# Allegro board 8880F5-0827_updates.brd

Outline 581.66 x 429.26 mm; copper layers: TOP, L02_DGND, L03_SIGNAL, L04_DGND, L05_SIGNAL, L06_DGND, L07_SIGNAL, L08_DGND, L09_SIGNAL, L10_DGND, L11_POWER, L12_DGND, L13_POWER, L14_DGND, L15_POWER, L16_DGND, L17_5V, L18_CBIT, L19_DGND, L20_POWER, L21_DGND, L22_POWER, L23_DGND, L24_POWER, L25_DGND, L26_SIGNAL, L27_DGND, L28_SIGNAL, L29_DGND, L30_SIGNAL, L31_DGND, L32_SIGNAL, L33_DGND, BOTTOM. Coordinates in mm from the lower left corner of the outline.

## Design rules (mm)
net group DIFFPAIR0: nets D31702 D31704
net group DIFFPAIR1: nets D31706 D31708
net group DIFFPAIR2: nets D31710 D31712
net group DIFFPAIR3: nets D31714 D31716
net group DIFFPAIR4: nets D32102 D32104
net group DIFFPAIR5: nets D32106 D32108
net group DIFFPAIR6: nets D32110 D32112
net group DIFFPAIR7: nets D32114 D32116
net group DIFFPAIR8: nets D30102 D30104
net group DIFFPAIR9: nets D30106 D30108
net group DIFFPAIR10: nets D30110 D30112
net group DIFFPAIR11: nets D30114 D30116
net group DIFFPAIR12: nets D30502 D30504
net group DIFFPAIR13: nets D30506 D30508
net group DIFFPAIR14: nets D30510 D30512
net group DIFFPAIR15: nets D30514 D30516
net group DIFFPAIR16: nets D13102 D13104
net group DIFFPAIR17: nets D13114 D13116
net group DIFFPAIR18: nets D13101 D13103
net group DIFFPAIR19: nets D13113 D13115
net group DIFFPAIR20: nets D13202 D13204
net group DIFFPAIR21: nets D13206 D13208
net group DIFFPAIR22: nets D13210 D13212
net group DIFFPAIR23: nets D13214 D13216
net group DIFFPAIR24: nets D13201 D13203
net group DIFFPAIR25: nets D13205 D13207
net group DIFFPAIR26: nets D13209 D13211
net group DIFFPAIR27: nets D13213 D13215
net group DIFFPAIR28: nets D11902 D11904
net group DIFFPAIR29: nets D11901 D11903
net group DIFFPAIR30: nets D11914 D11916
net group DIFFPAIR31: nets D11913 D11915
net group DIFFPAIR32: nets D12002 D12004
net group DIFFPAIR33: nets D12006 D12008
net group DIFFPAIR34: nets D12010 D12012
net group DIFFPAIR35: nets D12014 D12016
net group DIFFPAIR36: nets D12001 D12003
net group DIFFPAIR37: nets D12005 D12007
net group DIFFPAIR38: nets D12009 D12011
net group DIFFPAIR39: nets D12013 D12015
net group DIFFPAIR40: nets D10802 D10804
net group DIFFPAIR41: nets D10806 D10808
net group DIFFPAIR42: nets D10810 D10812
net group DIFFPAIR43: nets D10814 D10816
net group DIFFPAIR44: nets D10801 D10803
net group DIFFPAIR45: nets D10805 D10807
net group DIFFPAIR46: nets D10809 D10811
net group DIFFPAIR47: nets D10813 D10815
net group DIFFPAIR48: nets D10702 D10704
net group DIFFPAIR49: nets D10701 D10703
net group DIFFPAIR50: nets D10714 D10716
net group DIFFPAIR51: nets D10713 D10715
net group DIFFPAIR52: nets D11013 D11015
net group DIFFPAIR53: nets D11014 D11016
net group DIFFPAIR54: nets D11001 D11003
net group DIFFPAIR55: nets D11002 D11004
net group DIFFPAIR56: nets D10913 D10915
net group DIFFPAIR57: nets D10914 D10916
net group DIFFPAIR58: nets D10909 D10911
net group DIFFPAIR59: nets D10910 D10912
net group DIFFPAIR60: nets D10905 D10907
net group DIFFPAIR61: nets D10906 D10908
net group DIFFPAIR62: nets D10901 D10903
net group DIFFPAIR63: nets D10902 D10904
net group DIFFPAIR77: nets S1_ISP14+ S1_ISP14-
net group DIFFPAIR91: nets S1_ISP00+ S1_ISP00-
net group DIFFPAIR105: nets S2_ISP14+ S2_ISP14-
net group DIFFPAIR119: nets S2_ISP00+ S2_ISP00-
net group DIFFPAIR133: nets S4_ISP14+ S4_ISP14-
net group DIFFPAIR147: nets S4_ISP00+ S4_ISP00-
net group DIFFPAIR161: nets S3_ISP14+ S3_ISP14-
net group DIFFPAIR175: nets S3_ISP00+ S3_ISP00-
net group DIFFPAIR176: nets D12206 D12208
net group DIFFPAIR177: nets D12313 D12315
net group DIFFPAIR178: nets D12210 D12212
net group DIFFPAIR179: nets D11806 D11808
net group DIFFPAIR180: nets D11805 D11807
net group DIFFPAIR181: nets D12310 D12312
net group DIFFPAIR182: nets D11810 D11812
net group DIFFPAIR183: nets D11802 D11804
net group DIFFPAIR184: nets D11910 D11912
net group DIFFPAIR185: nets D11909 D11911
net group DIFFPAIR186: nets D11906 D11908
net group DIFFPAIR187: nets D11801 D11803
net group DIFFPAIR188: nets D11813 D11815
net group DIFFPAIR189: nets D11809 D11811
net group DIFFPAIR190: nets D12302 D12304
net group DIFFPAIR191: nets D12305 D12307
net group DIFFPAIR192: nets D12301 D12303
net group DIFFPAIR193: nets D12205 D12207
net group DIFFPAIR194: nets D12209 D12211
net group DIFFPAIR195: nets D12309 D12311
net group DIFFPAIR196: nets D12314 D12316
net group DIFFPAIR197: nets D12213 D12215
net group DIFFPAIR198: nets D12214 D12216
net group DIFFPAIR199: nets D12201 D12203
net group DIFFPAIR200: nets D12202 D12204
net group DIFFPAIR201: nets D11905 D11907
net group DIFFPAIR202: nets D10610 D10612
net group DIFFPAIR203: nets D10609 D10611
net group DIFFPAIR204: nets D10606 D10608
net group DIFFPAIR205: nets D10605 D10607
net group DIFFPAIR206: nets D10313 D10315
net group DIFFPAIR207: nets D10314 D10316
net group DIFFPAIR208: nets D10305 D10307
net group DIFFPAIR209: nets D10302 D10304
net group DIFFPAIR210: nets D10214 D10216
net group DIFFPAIR211: nets D10213 D10215
net group DIFFPAIR212: nets D10201 D10203
net group DIFFPAIR213: nets D10202 D10204
net group DIFFPAIR214: nets D10613 D10615
net group DIFFPAIR215: nets D10206 D10208
net group DIFFPAIR216: nets D10205 D10207
net group DIFFPAIR217: nets D10209 D10211
net group DIFFPAIR218: nets D10306 D10308
net group DIFFPAIR219: nets D10210 D10212
net group DIFFPAIR220: nets D10301 D10303
net group DIFFPAIR221: nets D10309 D10311
net group DIFFPAIR222: nets D10614 D10616
net group DIFFPAIR223: nets D10601 D10603
net group DIFFPAIR224: nets D10602 D10604
net group DIFFPAIR225: nets D10705 D10707
net group DIFFPAIR226: nets D10706 D10708
net group DIFFPAIR227: nets D10710 D10712
net group DIFFPAIR228: nets D11213 D11215
net group DIFFPAIR229: nets D11206 D11208
net group DIFFPAIR230: nets D11209 D11211
net group DIFFPAIR231: nets D11610 D11612
net group DIFFPAIR232: nets D11601 D11603
net group DIFFPAIR233: nets D11602 D11604
net group DIFFPAIR234: nets D11605 D11607
net group DIFFPAIR235: nets D11006 D11008
net group DIFFPAIR236: nets D11113 D11115
net group DIFFPAIR237: nets D11110 D11112
net group DIFFPAIR238: nets D11009 D11011
net group DIFFPAIR239: nets D11010 D11012
net group DIFFPAIR240: nets D11005 D11007
net group DIFFPAIR241: nets D11613 D11615
net group DIFFPAIR242: nets D11606 D11608
net group DIFFPAIR243: nets D11201 D11203
net group DIFFPAIR244: nets D11210 D11212
net group DIFFPAIR245: nets D11205 D11207
net group DIFFPAIR246: nets D11202 D11204
net group DIFFPAIR247: nets D11609 D11611
net group DIFFPAIR248: nets D11114 D11116
net group DIFFPAIR249: nets D11101 D11103
net group DIFFPAIR250: nets D11106 D11108
net group DIFFPAIR251: nets D11109 D11111
net group DIFFPAIR252: nets D11214 D11216
net group DIFFPAIR253: nets D11105 D11107
net group DIFFPAIR254: nets D12913 D12915
net group DIFFPAIR255: nets D12909 D12911
net group DIFFPAIR256: nets D12905 D12907
net group DIFFPAIR257: nets D12901 D12903
net group DIFFPAIR258: nets D12906 D12908
net group DIFFPAIR259: nets D12910 D12912
net group DIFFPAIR260: nets D12902 D12904
net group DIFFPAIR261: nets D12914 D12916
net group DIFFPAIR262: nets D11413 D11415
net group DIFFPAIR263: nets D11414 D11416
net group DIFFPAIR264: nets D11313 D11315
net group DIFFPAIR265: nets D11309 D11311
net group DIFFPAIR266: nets D11314 D11316
net group DIFFPAIR267: nets D11405 D11407
net group DIFFPAIR268: nets D11410 D11412
net group DIFFPAIR269: nets D11501 D11503
net group DIFFPAIR270: nets D11406 D11408
net group DIFFPAIR271: nets D11505 D11507
net group DIFFPAIR272: nets D11506 D11508
net group DIFFPAIR273: nets D11502 D11504
net group DIFFPAIR274: nets D11310 D11312
net group DIFFPAIR275: nets D11302 D11304
net group DIFFPAIR276: nets D11306 D11308
net group DIFFPAIR277: nets D11305 D11307
net group DIFFPAIR278: nets D11301 D11303
net group DIFFPAIR279: nets D11401 D11403
net group DIFFPAIR280: nets D11402 D11404
net group DIFFPAIR281: nets D11102 D11104
net group DIFFPAIR282: nets D10709 D10711
net group DIFFPAIR283: nets D11814 D11816

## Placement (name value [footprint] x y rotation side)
BD29  BD120-3A-S8  [FB0805]  129.54 134.62 180 bottom
BD30  BD120-3A-S8  [FB0805]  129.54 146.05 180 bottom
BD31  BD120-3A-S8  [FB0805]  129.54 142.24 0 bottom
BD32  BD120-3A-S8  [FB0805]  513.08 238.76 180 bottom
BD33  BD120-3A-S8  [FB0805]  513.08 242.57 180 bottom
BD34  BD120-3A-S8  [FB0805]  453.64 145.54 0 bottom
BD35  BD120-3A-S8  [FB0805]  453.64 137.92 180 bottom
BD36  BD120-3A-S8  [FB0805]  129.54 138.43 180 bottom
BD37  BD120-3A-S8  [FB0805]  453.64 130.3 180 bottom
BD38  BD120-3A-S8  [FB0805]  513.08 242.57 180 bottom
BD39  BD120-3A-S8  [FB0805]  453.64 141.73 0 bottom
BD40  BD120-3A-S8  [FB0805]  453.64 134.11 180 bottom
BD41  BD120-3A-S8  [FB0805]  513.08 234.95 180 bottom
BD42  BD120-3A-S8  [FB0805]  513.08 231.14 180 bottom
BD43  BD120-3A-S8  [FB0805]  513.08 227.33 180 bottom
BD44  BD120-3A-S8  [FB0805]  129.54 149.86 180 bottom
BR902  330-1-S4  [R0402]  36.83 133.35 270 bottom
C3  0.1U-16-X-S4-MU  [C0402]  184.15 132.33 180 bottom
C4  0.1U-16-X-S4-MU  [C0402]  181.61 132.33 180 bottom
C5  22P-50-N-S4-AVX  [C0402]  221.21 277.48 90 bottom
C6  22P-50-N-S4-AVX  [C0402]  221.21 271.16 270 bottom
C7  0.1U-16-X-S4-MU  [C0402]  110.74 230.12 0 bottom
C8  0.1U-16-X-S4-MU  [C0402]  104.14 215.5 180 bottom
C9  0.1U-16-X-S4-MU  [C0402]  104.24 229.1 180 bottom
CA1  NC/10U-10-X6S-S6-MU  [C0603]  186.05 292.1 0 bottom
CA2  NC/47U-10-X5R-S8-TDK  [C0805]  186.16 294 0 bottom
CA3  NC/10U-10-X6S-S6-MU  [C0603]  174.62 292.1 180 bottom
CA4  NC/47U-10-X5R-S8-TDK  [C0805]  174.52 294 180 bottom
CA5  NC/10U-10-X6S-S6-MU  [C0603]  117.47 290.83 180 bottom
CA6  NC/47U-10-X5R-S8-TDK  [C0805]  117.37 292.74 180 bottom
CA7  NC/10U-10-X6S-S6-MU  [C0603]  169.54 292.1 0 bottom
CA8  NC/47U-10-X5R-S8-TDK  [C0805]  169.65 294 0 bottom
CA9  NC/10U-10-X6S-S6-MU  [C0603]  158.11 292.1 180 bottom
CA10  NC/47U-10-X5R-S8-TDK  [C0805]  158.01 294 180 bottom
CA11  NC/10U-10-X6S-S6-MU  [C0603]  186.05 275.59 0 bottom
CA12  NC/47U-10-X5R-S8-TDK  [C0805]  186.16 277.5 0 bottom
CA13  NC/47U-10-X5R-S8-TDK  [C0805]  202.16 294 0 bottom
CA14  NC/10U-10-X6S-S6-MU  [C0603]  202.06 292.1 0 bottom
CA15  NC/47U-10-X5R-S8-TDK  [C0805]  190.53 294 180 bottom
CA16  NC/10U-10-X6S-S6-MU  [C0603]  190.63 292.1 180 bottom
CA17  NC/47U-10-X5R-S8-TDK  [C0805]  169.65 277.5 0 bottom
CA18  NC/10U-10-X6S-S6-MU  [C0603]  169.54 275.59 0 bottom
CA19  NC/47U-10-X5R-S8-TDK  [C0805]  100.34 249.52 180 bottom
CA20  NC/10U-10-X6S-S6-MU  [C0603]  100.44 247.61 180 bottom
CA21  10U-10-X6S-S6-MU  [C0603]  186.05 289.56 0 bottom
CA22  10U-10-X6S-S6-MU  [C0603]  174.62 289.56 180 bottom
CA23  10U-10-X6S-S6-MU  [C0603]  117.47 288.29 180 bottom
CA24  10U-10-X6S-S6-MU  [C0603]  169.54 289.56 0 bottom
CA25  10U-10-X6S-S6-MU  [C0603]  158.11 289.56 180 bottom
CA26  10U-10-X6S-S6-MU  [C0603]  186.05 273.05 0 bottom
CA27  10U-10-X6S-S6-MU  [C0603]  202.06 289.56 0 bottom
CA28  10U-10-X6S-S6-MU  [C0603]  190.63 289.56 180 bottom
CA29  10U-10-X6S-S6-MU  [C0603]  169.54 273.05 0 bottom
CA30  NC/47U-10-X5R-S8-TDK  [C0805]  95.47 249.57 180 bottom
CA31  10U-10-X6S-S6-MU  [C0603]  95.57 247.66 180 bottom
CA32  NC/10U-10-X6S-S6-MU  [C0603]  202.06 275.59 0 bottom
CA33  NC/47U-10-X5R-S8-TDK  [C0805]  202.16 277.5 0 bottom
CA34  10U-10-X6S-S6-MU  [C0603]  202.06 273.05 0 bottom
CA35  NC/10U-10-X6S-S6-MU  [C0603]  174.62 275.59 180 bottom
CA36  NC/47U-10-X5R-S8-TDK  [C0805]  174.52 277.5 180 bottom
CA37  10U-10-X6S-S6-MU  [C0603]  174.62 273.05 180 bottom
CA38  NC/10U-10-X6S-S6-MU  [C0603]  158.11 275.59 180 bottom
CA39  NC/47U-10-X5R-S8-TDK  [C0805]  158.01 277.5 180 bottom
CA40  10U-10-X6S-S6-MU  [C0603]  158.11 273.05 180 bottom
CB1  0.1U-25-X-S6  [C0603]  116.84 130.81 0 bottom
CB2  10U-16-T-SA  [CODE_A]  116.84 128.27 0 bottom
CB3  0.1U-25-X-S6  [C0603]  472.44 130.81 0 bottom
CB4  10U-16-T-SA  [CODE_A]  472.44 128.27 0 bottom
CB5  0.1U-25-X-S6  [C0603]  556.51 300.99 0 bottom
CB6  10U-16-T-SA  [CODE_A]  556.51 298.45 0 bottom
CB7  0.1U-25-X-S6  [C0603]  223.52 298.45 0 bottom
CB8  10U-16-T-SA  [CODE_A]  223.52 295.91 0 bottom
CB9  0.1U-25-X-S6  [C0603]  23.01 130.71 0 bottom
CB10  10U-25-X7R-SA  [C1206]  22.86 128.27 0 bottom
CB11  0.1U-25-X-S6  [C0603]  484.02 130.71 0 bottom
CB12  10U-25-X7R-SA  [C1206]  483.87 128.27 0 bottom
CB13  0.1U-25-X-S6  [C0603]  547.52 300.89 0 bottom
CB14  10U-25-X7R-SA  [C1206]  547.37 298.45 0 bottom
CB15  0.1U-25-X-S6  [C0603]  12.45 262.13 0 bottom
CB16  10U-25-X7R-SA  [C1206]  12.3 259.69 0 bottom
CB19  0.1U-25-X7R-S4-MU  [C0402]  215.9 17.78 180 bottom
CC1  0.47U-10-X6S-S2-TY  [C0201]  237.98 224.12 90 bottom
CC2  4.7U-10-X6T-S4-MU  [C0402]  236.32 222.4 270 bottom
CC4  0.47U-10-X6S-S2-TY  [C0201]  229.81 247.93 0 bottom
CC6  0.47U-10-X6S-S2-TY  [C0201]  250.17 224.12 90 bottom
CC7  0.47U-10-X6S-S2-TY  [C0201]  229.81 246.66 0 bottom
CC8  0.47U-10-X6S-S2-TY  [C0201]  263.63 224.12 90 bottom
CC9  0.47U-10-X6S-S2-TY  [C0201]  254.61 266.16 270 bottom
CC11  0.47U-10-X6S-S2-TY  [C0201]  251.06 224.12 90 bottom
CC13  0.47U-10-X6S-S2-TY  [C0201]  256.77 224.12 90 bottom
CC15  4.7U-2.5-X6S-S2-MU  [C0201]  259.65 264.95 90 bottom
CC16  NC/4.7U-2.5-X6S-S2-MU  [C0201]  271.64 249.5 0 bottom
CC17  4.7U-2.5-X6S-S2-MU  [C0201]  229.81 253.69 0 bottom
CC19  0.47U-10-X6S-S2-TY  [C0201]  252.83 266.16 270 bottom
CC20  4.7U-10-X6T-S4-MU  [C0402]  254.11 267.66 0 bottom
CC22  0.47U-10-X6S-S2-TY  [C0201]  251.05 266.16 270 bottom
CC23  4.7U-10-X6T-S4-MU  [C0402]  250.34 253.09 270 bottom
CC25  0.47U-10-X6S-S2-TY  [C0201]  272.85 245.18 180 bottom
CC26  0.47U-10-X6S-S2-TY  [C0201]  253.72 266.16 270 bottom
CC27  0.47U-10-X6S-S2-TY  [C0201]  272.85 249.5 180 bottom
CC28  0.47U-10-X6S-S2-TY  [C0201]  259.65 266.16 270 bottom
CC29  0.47U-10-X6S-S2-TY  [C0201]  231.03 253.69 180 bottom
CC30  0.47U-10-X6S-S2-TY  [C0201]  229.81 243.41 0 bottom
CC31  0.47U-10-X6S-S2-TY  [C0201]  249.28 224.12 90 bottom
CC32  0.47U-10-X6S-S2-TY  [C0201]  262.36 224.12 90 bottom
CC33  0.47U-10-X6S-S2-TY  [C0201]  272.85 243.91 180 bottom
CC34  0.47U-10-X6S-S2-TY  [C0201]  251.94 266.16 270 bottom
CC35  0.47U-10-X6S-S2-TY  [C0201]  272.85 241.37 180 bottom
CC36  0.47U-10-X6S-S2-TY  [C0201]  272.85 242.64 180 bottom
CC37  0.47U-10-X6S-S2-TY  [C0201]  247.57 264.95 90 bottom
CC38  NC/4.7U-2.5-X6S-S2-MU  [C0201]  247.57 266.16 270 bottom
CC39  0.47U-10-X6S-S2-TY  [C0201]  231.03 249.2 180 bottom
CC40  4.7U-2.5-X6S-S2-MU  [C0201]  258.5 246.67 180 bottom
CC41  4.7U-2.5-X6S-S2-MU  [C0201]  229.81 249.2 0 bottom
CC42  4.7U-2.5-X6S-S2-MU  [C0201]  251.54 253.03 90 bottom
CD1  0.1U-10-X7R-S2-MU  [C0201]  237.98 225.34 270 top
CD3  0.1U-10-X7R-S2-MU  [C0201]  271.64 241.37 0 top
CD4  0.1U-10-X7R-S2-MU  [C0201]  254.61 264.95 90 top
CD5  0.1U-10-X7R-S2-MU  [C0201]  263.63 225.34 270 top
CD6  0.1U-10-X7R-S2-MU  [C0201]  231.03 246.66 180 top
CD7  0.1U-10-X7R-S2-MU  [C0201]  271.64 242.64 0 top
CD8  0.1U-10-X7R-S2-MU  [C0201]  251.06 225.34 270 top
CD9  0.1U-10-X7R-S2-MU  [C0201]  256.77 225.34 270 top
CD10  0.1U-10-X7R-S2-MU  [C0201]  271.64 249.5 0 top
CD11  0.1U-10-X7R-S2-MU  [C0201]  259.65 264.95 90 top
CD12  0.1U-10-X7R-S2-MU  [C0201]  231.03 253.69 180 top
CD13  0.1U-10-X7R-S2-MU  [C0201]  252.83 264.95 90 top
CD14  0.1U-10-X7R-S2-MU  [C0201]  251.05 264.95 90 top
CD15  0.1U-10-X7R-S2-MU  [C0201]  271.64 245.18 0 top
CD16  0.1U-10-X7R-S2-MU  [C0201]  253.72 264.95 90 top
CD17  0.1U-10-X7R-S2-MU  [C0201]  231.03 247.93 180 top
CD18  0.1U-10-X7R-S2-MU  [C0201]  251.94 264.95 90 top
CD19  0.1U-10-X7R-S2-MU  [C0201]  231.03 243.41 180 top
CD20  0.1U-10-X7R-S2-MU  [C0201]  271.64 243.91 0 top
CD21  0.1U-10-X7R-S2-MU  [C0201]  262.36 225.34 270 top
CD22  0.1U-10-X7R-S2-MU  [C0201]  249.28 225.34 270 top
CD23  0.1U-10-X7R-S2-MU  [C0201]  250.17 225.34 270 top
CD24  0.1U-10-X7R-S2-MU  [C0201]  247.57 264.95 90 top
CD25  0.1U-10-X7R-S2-MU  [C0201]  231.03 249.2 180 top
CSDPS225  V93K_CSDPS_DPS32  [PG_VG93K_PF_DPS32_G8D225]  254 331.47 0 top
CSDPS229  V93K_CSDPS_DPS32  [PG_VG93K_PF_DPS32_G8D229]  180.34 331.47 0 top
CSDPS425  V93K_CSDPS_DPS32  [PG_VG93K_PF_DPS32_G8D425]  254 341.63 0 top
CSDPS429  V93K_CSDPS_DPS32  [PG_VG93K_PF_DPS32_G8D429]  180.34 341.63 0 top
D101/D501  V93K_PS1600 HD  [PG_VG93K_F_HSM_G1D101_501_ND]  327.66 97.79 0 top
D102  V93K_CH  [PG_VG93K_F_G1D102]  327.66 77.47 0 top
D103  V93K_CH  [PG_VG93K_F_G1D103]  327.66 57.15 0 top
D104  V93K_CH  [PG_VG93K_F_G1D104]  327.66 36.83 0 top
D105/D505  V93K_PS1600 HD  [PG_VG93K_F_HSM_G1D105_505_ND]  401.32 97.79 0 top
D106  V93K_CH  [PG_VG93K_F_G1D106]  401.32 77.47 0 top
D107  V93K_CH  [PG_VG93K_F_G1D107]  401.32 57.15 0 top
D108  V93K_CH  [PG_VG93K_F_G1D108]  401.32 36.83 0 top
D109  V93K_CH  [PG_VG93K_F_G2D109]  401.32 331.47 0 top
D110  V93K_CH  [PG_VG93K_F_G2D110]  401.32 351.79 0 top
D111  V93K_CH  [PG_VG93K_F_G2D111]  401.32 372.11 0 top
D112  V93K_CH  [PG_VG93K_F_G2D112]  401.32 392.43 0 top
D113  V93K_CH  [PG_VG93K_F_G2D113]  327.66 331.47 0 top
D114  V93K_CH  [PG_VG93K_F_G2D114]  327.66 351.79 0 top
D115  V93K_CH  [PG_VG93K_F_G2D115]  327.66 372.11 0 top
D116  V93K_CH  [PG_VG93K_F_G2D116]  327.66 392.43 0 top
D117/D517  V93K_PS1600 HD  [PG_VG93K_F_HSM_G3D117_517_ND]  180.34 97.79 0 top
D118  V93K_CH  [PG_VG93K_F_G3D118]  180.34 77.47 0 top
D119  V93K_CH  [PG_VG93K_F_G3D119]  180.34 57.15 0 top
D120  V93K_CH  [PG_VG93K_F_G3D120]  180.34 36.83 0 top
D121/D521  V93K_PS1600 HD  [PG_VG93K_F_HSM_G3D121_521_ND]  254 97.79 0 top
D122  V93K_CH  [PG_VG93K_F_G3D122]  254 77.47 0 top
D123  V93K_CH  [PG_VG93K_F_G3D123]  254 57.15 0 top
D124  V93K_CH  [PG_VG93K_F_G3D124]  254 36.83 0 top
D125  V93K_CH  [PG_VG93K_F_G4D125]  33.02 97.79 0 top
D126  V93K_CH  [PG_VG93K_F_G4D126]  33.02 77.47 0 top
D127  V93K_CH  [PG_VG93K_F_G4D127]  33.02 57.15 0 top
D128  V93K_CH  [PG_VG93K_F_G4D128]  33.02 36.83 0 top
D129  V93K_CH  [PG_VG93K_F_G4D129]  106.68 97.79 0 top
D130  V93K_CH  [PG_VG93K_F_G4D130]  106.68 77.47 0 top
D131  V93K_CH  [PG_VG93K_F_G4D131]  106.68 57.15 0 top
D132  V93K_CH  [PG_VG93K_F_G4D132]  106.68 36.83 0 top
D231  V93K_CH  [PG_VG93K_F_G8D231]  180.34 372.11 0 top
D301  V93K_CH  [PG_VG93K_F_G1D301]  327.66 87.63 0 top
D302  V93K_CH  [PG_VG93K_F_G1D302]  327.66 67.31 0 top
D305  V93K_CH  [PG_VG93K_F_G1D305]  401.32 87.63 0 top
D306  V93K_CH  [PG_VG93K_F_G1D306]  401.32 67.31 0 top
D309  V93K_PSSL  [PG_VG93K_F_PSSL_G2D309_ND]  401.32 341.63 0 top
D313  V93K_PSSL  [PG_VG93K_F_PSSL_G2D313_ND]  327.66 341.63 0 top
D317  V93K_CH  [PG_VG93K_F_G3D317]  180.34 87.63 0 top
D318  V93K_CH  [PG_VG93K_F_G3D318]  180.34 67.31 0 top
D321  V93K_CH  [PG_VG93K_F_G3D321]  254 87.63 0 top
D322  V93K_CH  [PG_VG93K_F_G3D322]  254 67.31 0 top
D431  V93K_CH  [PG_VG93K_F_G8D431]  180.34 382.27 0 top
DPS1  V93K_DPS  [PG_VG93K_F_G1DPS1]  401.32 16.51 0 top
DPS2  V93K_DPS  [PG_VG93K_F_G2DPS2]  327.66 412.75 0 top
DPS3  V93K_DPS  [PG_VG93K_F_G3DPS3]  254 16.51 0 top
DPS8  V93K_DPS  [PG_VG93K_F_G8DPS8]  180.34 412.75 0 top
FD1  -  [FD_040_V2]  159.82 131.98 0 top
FD2  -  [FD_040_V2]  423.24 131.98 0 top
FD3  -  [FD_040_V2]  423.24 297.28 0 top
FD4  -  [FD_040_V2]  156.51 297.46 0 top
FD5  -  [FD_040_V2]  159.82 131.98 180 bottom
FD6  -  [FD_040_V2]  423.24 131.98 180 bottom
FD7  -  [FD_040_V2]  423.24 297.28 180 bottom
FD8  -  [FD_040_V2]  156.51 297.46 180 bottom
FD9  -  [FD_040_V2]  570.23 128.27 180 bottom
FD10  -  [FD_040_V2]  570.23 300.99 0 top
FD11  -  [FD_040_V2]  570.23 300.99 180 bottom
FD12  -  [FD_040_V2]  11.43 300.99 0 top
FD13  -  [FD_040_V2]  11.43 300.99 180 bottom
FD14  -  [FD_040_V2]  11.43 127 0 top
FD15  -  [FD_040_V2]  11.43 127 180 bottom
FD16  -  [FD_040_V2]  570.23 128.27 0 top
GND1  TP01  [TP_040_T]  173.57 294 0 top
GND2  TP01  [TP_040_T]  187.11 294 180 top
GND3  TP01  [TP_040_T]  116.42 292.74 0 top
GND4  TP01  [TP_040_T]  157.06 294 0 top
GND5  TP01  [TP_040_T]  170.6 294 180 top
GND6  TP01  [TP_040_T]  173.57 277.5 0 top
GND7  TP01  [TP_040_T]  203.11 294 180 top
GND8  TP01  [TP_040_T]  189.58 294 0 top
GND9  TP01  [TP_040_T]  170.6 277.5 180 top
GND10  TP01  [TP_040_T]  99.36 249.46 0 top
GND11  TP01  [TP_040_T]  94.49 249.52 0 top
GND12  TP01  [TP_040_T]  203.11 277.5 180 top
GND13  TP01  [TP_040_T]  187.11 277.5 180 top
GND14  TP01  [TP_040_T]  157.06 277.5 0 top
HX8880-F05  REF-CODE-CHIP  [CHIP_CODE]  559.05 279.65 0 top
J1  HDR-2X1-M  [JP_2P_100]  110.24 232.41 270 bottom
J2  HDR-3X1-M  [JP_3P_100]  88.76 205.43 90 bottom
J3  HDR-3X1-M  [JP_3P_100]  88.76 219.15 90 bottom
J4  HDR-2X1-M  [JP_2P_100]  96.27 231.39 90 bottom
J5  HDR-2X1-M  [JP_2P_100]  96.27 243.08 90 bottom
JG_220919AA01  REF-CODE-SOCKET  [SOCKET_CODE]  559.05 284.73 0 top
JG_220919AA02  REF-CODE-SOCKET  [SOCKET_CODE]  559.05 287.27 0 top
K1  G6K-2F-RF-T-5V-SPECIAL  [RL_G6K2FRT_8P_5V_GR]  347.73 292.86 0 bottom
K2  G6K-2F-RF-T-5V-SPECIAL  [RL_G6K2FRT_8P_5V_GR]  334.26 292.86 0 bottom
K3  G6K-2F-RF-T-5V-SPECIAL  [RL_G6K2FRT_8P_5V_GR]  320.8 292.86 0 bottom
K4  G6K-2F-RF-T-5V-SPECIAL  [RL_G6K2FRT_8P_5V_GR]  289.56 276.1 180 bottom
K5  G6K-2F-RF-T-5V-SPECIAL  [RL_G6K2FRT_8P_5V_GR]  307.59 292.86 0 bottom
K6  G6K-2F-RF-T-5V-SPECIAL  [RL_G6K2FRT_8P_5V_GR]  294.39 292.86 0 bottom
K7  G6K-2F-RF-T-5V-SPECIAL  [RL_G6K2FRT_8P_5V_GR]  280.92 292.86 0 bottom
K8  G6K-2F-RF-T-5V-SPECIAL  [RL_G6K2FRT_8P_5V_GR]  267.46 292.86 0 bottom
K9  UA2-5NJ-A-V3  [RL_NECUA2_5V_V3]  219.96 235.46 90 bottom
K10  UA2-5NJ-A-V3  [RL_NECUA2_5V_V3]  111.76 237.24 0 bottom
K11  G6K-2F-RF-T-5V-SPECIAL  [RL_G6K2FRT_8P_5V_GR]  254.25 292.86 0 bottom
K12  UA2-5NJ-A-V3  [RL_NECUA2_5V_V3]  219.96 246.89 90 bottom
K13  UA2-5NJ-A-V3  [RL_NECUA2_5V_V3]  123.7 229.62 180 bottom
K14  UA2-5NJ-A-V3  [RL_NECUA2_5V_V3]  112.01 220.73 180 bottom
K15  UA2-5NJ-A-V3  [RL_NECUA2_5V_V3]  123.99 213.19 180 bottom
K16  G6K-2F-RF-T-5V-SPECIAL  [RL_G6K2FRT_8P_5V_GR]  241.05 292.61 180 bottom
K17  G6K-2F-RF-T-5V-SPECIAL  [RL_G6K2FRT_8P_5V_GR]  188.47 260.35 270 bottom
K18  UB2-5NU-B  [RL_NECUB2_5V]  228.45 274.32 0 bottom
K19  UA2-5NJ-A-V3  [RL_NECUA2_5V_V3]  112.01 213.11 180 bottom
K20  UA2-5NJ-A-V3  [RL_NECUA2_5V_V3]  123.95 220.73 180 bottom
K21  G6K-2F-RF-T-5V-SPECIAL  [RL_G6K2FRT_8P_5V_GR]  204.98 260.35 270 bottom
K22  G6K-2F-RF-T-5V-SPECIAL  [RL_G6K2FRT_8P_5V_GR]  205.23 232.92 270 bottom
K23  G6K-2F-RF-T-5V-SPECIAL  [RL_G6K2FRT_8P_5V_GR]  171.7 219.2 270 bottom
K24  G6K-2F-RF-T-5V-SPECIAL  [RL_G6K2FRT_8P_5V_GR]  188.47 232.92 270 bottom
K25  G6K-2F-RF-T-5V-SPECIAL  [RL_G6K2FRT_8P_5V_GR]  205.23 246.63 270 bottom
K26  G6K-2F-RF-T-5V-SPECIAL  [RL_G6K2FRT_8P_5V_GR]  171.7 232.92 270 bottom
K27  G6K-2F-RF-T-5V-SPECIAL  [RL_G6K2FRT_8P_5V_GR]  188.47 246.63 270 bottom
K28  UA2-5NJ-A-V3  [RL_NECUA2_5V_V3]  100.33 237.24 0 bottom
K29  G6K-2F-RF-T-5V-SPECIAL  [RL_G6K2FRT_8P_5V_GR]  171.7 260.35 270 bottom
K30  G6K-2F-RF-T-5V-SPECIAL  [RL_G6K2FRT_8P_5V_GR]  171.7 246.63 270 bottom
K31  EC2-5NJ-A  [RL_NECEC2_10P_5V]  196.34 276.86 90 bottom
K33  NC/UA2-5NJ-A-V3  [RL_NECUA2_5V_V3]  123.7 237.24 180 bottom
K34  EC2-5NJ-A  [RL_NECEC2_10P_5V]  180.34 293.37 90 bottom
K36  EC2-5NJ-A  [RL_NECEC2_10P_5V]  123.19 292.1 90 bottom
K37  EC2-5NJ-A  [RL_NECEC2_10P_5V]  163.83 293.37 90 bottom
K39  EC2-5NJ-A  [RL_NECEC2_10P_5V]  180.34 276.86 90 bottom
K40  EC2-5NJ-A  [RL_NECEC2_10P_5V]  196.34 293.37 90 bottom
K42  EC2-5NJ-A  [RL_NECEC2_10P_5V]  163.83 276.86 90 bottom
K43  G6K-2F-RF-T-5V-SPECIAL  [RL_G6K2FRT_8P_5V_GR]  269.49 276.1 180 bottom
LD902  LDG-2-S8  [LED_0805]  36.83 130.81 90 top
LOGO1  -  [LOGO_KT_KSMT]  538.48 154.94 0 top
LOGO2  LOGO_HX_Himax  [LOGO_HX_HIMAX]  518.16 138.43 0 top
LQFP176-20X20-P0.4  REF-CODE-CHIP  [CHIP_CODE]  559.05 282.19 0 top
NOREF  -  []  294.94 296.86 0 top
NOREF#2  -  []  463.11 230.2 0 top
NOREF#3  -  []  333.4 265.56 90 top
NOREF#4  -  []  331.62 264.35 90 top
NOREF#5  -  []  385.19 281.11 0 top
NOREF#6  -  []  271.04 244.23 0 top
NOREF#7  -  []  459.28 227 90 top
NOREF#8  -  []  351.04 189.18 0 top
NOREF#9  -  []  218.16 177.06 0 top
NOREF#10  -  []  385.19 265.11 0 top
NOREF#11  -  []  342.68 223.52 90 top
NOREF#12  -  []  108.01 214.71 0 top
NOREF#13  -  []  511.59 273.87 90 top
NOREF#14  -  []  381.2 258.38 90 top
NOREF#15  -  []  475.36 127 90 top
NOREF#16  -  []  184.47 206.29 90 top
NOREF#17  -  []  422.95 163.69 90 top
NOREF#18  -  []  352.55 249.5 0 top
NOREF#19  -  []  167.7 214 90 top
NOREF#20  -  []  382.82 163.39 0 top
NOREF#21  -  []  478.57 293.82 90 top
NOREF#22  -  []  168.13 145.38 90 top
NOREF#23  -  []  201.49 173.11 90 top
NOREF#24  -  []  449.99 174.46 0 top
NOREF#25  -  []  373.87 188.15 0 top
NOREF#26  -  []  396.28 146.93 90 top
NOREF#27  -  []  310.43 189.52 0 top
NOREF#28  -  []  250.17 165.04 90 top
NOREF#29  -  []  465.45 276.41 90 top
NOREF#30  -  []  392.04 241.11 90 top
NOREF#31  -  []  387.08 154.88 0 top
NOREF#32  -  []  271.04 184.23 0 top
NOREF#33  -  []  290.64 288.86 0 top
NOREF#34  -  []  230.43 188.88 90 top
NOREF#35  -  []  172.08 291.65 90 top
NOREF#36  -  []  251.62 205.56 0 top
NOREF#37  -  []  246.23 233.13 0 top
NOREF#38  -  []  400.25 148.15 90 top
NOREF#39  -  []  320.42 139.64 0 top
NOREF#40  -  []  419.47 241.11 90 top
NOREF#41  -  []  253.4 205.56 90 top
NOREF#42  -  []  322.23 173.13 0 top
NOREF#43  -  []  127.95 187.53 0 top
NOREF#44  -  []  304.65 211.67 0 top
NOREF#45  -  []  379.52 171.39 0 top
NOREF#46  -  []  473.79 196.21 0 top
NOREF#47  -  []  295.96 188.49 0 top
NOREF#48  -  []  182.82 148.4 90 top
NOREF#49  -  []  209.23 202.99 90 top
NOREF#50  -  []  304.61 131.64 0 top
NOREF#51  -  []  471.21 219.38 90 top
NOREF#52  -  []  343.83 231.63 90 top
NOREF#53  -  []  184.47 163.2 90 top
NOREF#54  -  []  96.33 238.84 0 top
NOREF#55  -  []  167.7 244.98 90 top
NOREF#56  -  []  413.96 182.44 90 top
NOREF#57  -  []  184.47 214 0 top
NOREF#58  -  []  75.98 290.38 90 top
NOREF#59  -  []  175.7 189.02 90 top
NOREF#60  -  []  249.6 163.52 90 top
NOREF#61  -  []  301.56 242.89 0 top
NOREF#62  -  []  209.08 256.4 90 top
NOREF#63  -  []  367.13 287.22 0 top
NOREF#64  -  []  392.04 257.11 90 top
NOREF#65  -  []  418.12 289.12 0 top
NOREF#66  -  []  230.43 253.37 90 top
NOREF#67  -  []  400.85 233.11 0 top
NOREF#68  -  []  352.25 241.05 90 top
NOREF#69  -  []  246.63 142.04 0 top
NOREF#70  -  []  352.24 249.18 90 top
NOREF#71  -  []  167.7 219.75 90 top
NOREF#72  -  []  194.09 160.4 90 top
NOREF#73  -  []  377.32 163.39 0 top
NOREF#74  -  []  310.41 183.09 90 top
NOREF#75  -  []  272.55 183.91 0 top
NOREF#76  -  []  199.59 158.5 0 top
NOREF#77  -  []  167.7 260.9 90 top
NOREF#78  -  []  453.88 186.77 0 top
NOREF#79  -  []  386.33 207.21 90 top
NOREF#80  -  []  319.33 236.03 0 top
NOREF#81  -  []  246.67 288.16 90 top
NOREF#82  -  []  418.12 273.37 0 top
NOREF#83  -  []  272.55 181.37 0 top
NOREF#84  -  []  230.73 247.93 0 top
NOREF#85  -  []  165.8 185.42 0 top
NOREF#86  -  []  461.96 217.98 0 top
NOREF#87  -  []  271.34 183.91 0 top
NOREF#88  -  []  383.09 257.11 0 top
NOREF#89  -  []  271.34 241.37 0 top
NOREF#90  -  []  385.19 257.11 0 top
NOREF#91  -  []  351.04 249.82 0 top
NOREF#92  -  []  401.89 180.15 0 top
NOREF#93  -  []  247.57 204.65 90 top
NOREF#94  -  []  229.21 188.88 0 top
NOREF#95  -  []  368.03 232.6 0 top
NOREF#96  -  []  396.55 257.37 0 top
NOREF#97  -  []  107.02 166.42 90 top
NOREF#98  -  []  222.11 180.71 0 top
NOREF#99  -  []  36.1 131.91 0 top
NOREF#100  -  []  182.82 189.04 90 top
NOREF#101  -  []  253.72 264.65 90 top
NOREF#102  -  []  272.25 244.86 90 top
NOREF#103  -  []  344.37 128.27 90 top
NOREF#104  -  []  342.68 163.52 90 top
NOREF#105  -  []  221.56 179.06 0 top
NOREF#106  -  []  353.35 288.31 90 top
NOREF#107  -  []  379.48 255.21 90 top
NOREF#108  -  []  392.47 224.4 90 top
NOREF#109  -  []  412.88 139.89 0 top
NOREF#110  -  []  413.71 148.15 90 top
NOREF#111  -  []  199.33 212.85 90 top
NOREF#112  -  []  279.7 155.38 0 top
NOREF#113  -  []  263.14 270.2 90 top
NOREF#114  -  []  229.51 187.93 0 top
NOREF#115  -  []  247.57 264.65 90 top
NOREF#116  -  []  420.15 131.34 90 top
NOREF#117  -  []  184.47 247.18 90 top
NOREF#118  -  []  96.58 195.15 0 top
NOREF#119  -  []  453.88 230.2 0 top
NOREF#120  -  []  118.99 166.5 90 top
NOREF#121  -  []  408.88 133.16 90 top
NOREF#122  -  []  242.23 233.13 90 top
NOREF#123  -  []  119.95 187.53 0 top
NOREF#124  -  []  394.66 258.64 90 top
NOREF#125  -  []  404.15 273.11 0 top
NOREF#126  -  []  303.84 288.86 0 top
NOREF#127  -  []  410.52 289.12 0 top
NOREF#128  -  []  451.68 214.96 0 top
NOREF#129  -  []  259.33 265.56 0 top
NOREF#130  -  []  253.4 205.55 0 top
NOREF#131  -  []  334.29 264.35 90 top
NOREF#132  -  []  419.47 289.12 90 top
NOREF#133  -  []  230.43 253.37 90 top
NOREF#134  -  []  259.97 264.35 90 top
NOREF#135  -  []  222.67 298 90 top
NOREF#136  -  []  201.49 165.4 90 top
NOREF#137  -  []  396.22 139.89 0 top
NOREF#138  -  []  217.83 234.63 90 top
NOREF#139  -  []  352.24 189.18 90 top
NOREF#140  -  []  272.24 243.59 90 top
NOREF#141  -  []  201.4 254.6 90 top
NOREF#142  -  []  402.14 146.88 0 top
NOREF#143  -  []  465.31 186.77 0 top
NOREF#144  -  []  425.23 180.72 90 top
NOREF#145  -  []  167.7 151.68 90 top
NOREF#146  -  []  210.86 201.29 90 top
NOREF#147  -  []  271.04 245.5 0 top
NOREF#148  -  []  331.05 264.65 90 top
NOREF#149  -  []  390.94 273.16 90 top
NOREF#150  -  []  303.56 233.86 90 top
NOREF#151  -  []  327.57 264.65 90 top
NOREF#152  -  []  199.59 145.03 90 top
NOREF#153  -  []  381.2 274.38 90 top
NOREF#154  -  []  182.57 158.5 0 top
NOREF#155  -  []  249.13 140.14 0 top
NOREF#156  -  []  475.04 239.09 0 top
NOREF#157  -  []  330.17 163.82 90 top
NOREF#158  -  []  184.47 165.4 90 top
NOREF#159  -  []  397.38 146.88 90 top
NOREF#160  -  []  300.36 188.49 0 top
NOREF#161  -  []  231.15 219.63 90 top
NOREF#162  -  []  249.28 223.82 90 top
NOREF#163  -  []  175.7 141.67 90 top
NOREF#164  -  []  371.48 241.11 0 top
NOREF#165  -  []  286.55 288.41 90 top
NOREF#166  -  []  297.71 276.09 0 top
NOREF#167  -  []  482.64 192.46 90 top
NOREF#168  -  []  251.62 265.55 0 top
NOREF#169  -  []  300.11 273.24 90 top
NOREF#170  -  []  266.49 143.19 0 top
NOREF#171  -  []  247.25 204.35 90 top
NOREF#172  -  []  327.25 205.56 0 top
NOREF#173  -  []  192.47 154.88 90 top
NOREF#174  -  []  387.39 265.11 0 top
NOREF#175  -  []  257.9 186.99 0 top
NOREF#176  -  []  286.81 272.1 0 top
NOREF#177  -  []  272.55 243.91 0 top
NOREF#178  -  []  259.88 288.31 90 top
NOREF#179  -  []  167.7 256.5 90 top
NOREF#180  -  []  351.04 189.82 0 top
NOREF#181  -  []  380.59 255.21 0 top
NOREF#182  -  []  100.98 195.15 0 top
NOREF#183  -  []  409.17 249.11 0 top
NOREF#184  -  []  121.9 238.84 0 top
NOREF#185  -  []  330.17 165.04 90 top
NOREF#186  -  []  518.38 259.9 90 top
NOREF#187  -  []  354.27 138.37 90 top
NOREF#188  -  []  333.4 265.55 0 top
NOREF#189  -  []  256.77 225.04 90 top
NOREF#190  -  []  406.65 255.47 90 top
NOREF#191  -  []  472.86 174.55 90 top
NOREF#192  -  []  237.98 223.82 90 top
NOREF#193  -  []  450.03 182.17 0 top
NOREF#194  -  []  351.83 288.91 90 top
NOREF#195  -  []  209.23 230.17 90 top
NOREF#196  -  []  331.62 265.56 0 top
NOREF#197  -  []  263.95 163.52 90 top
NOREF#198  -  []  167.7 165.4 90 top
NOREF#199  -  []  272.24 244.86 90 top
NOREF#200  -  []  256.77 165.04 90 top
NOREF#201  -  []  84.04 287.84 90 top
NOREF#202  -  []  168.13 213.45 90 top
NOREF#203  -  []  310.41 246.34 90 top
NOREF#204  -  []  485.36 292.02 90 top
NOREF#205  -  []  272.25 189.18 90 top
NOREF#206  -  []  230.41 246.34 90 top
NOREF#207  -  []  318.3 223.52 90 top
NOREF#208  -  []  309.21 253.37 0 top
NOREF#209  -  []  303.84 288.86 0 top
NOREF#210  -  []  254.29 205.55 0 top
NOREF#211  -  []  184.47 255.15 90 top
NOREF#212  -  []  374.88 217.11 0 top
NOREF#213  -  []  495.08 259.9 90 top
NOREF#214  -  []  223.56 245.29 90 top
NOREF#215  -  []  263.63 165.04 90 top
NOREF#216  -  []  192.47 189.02 90 top
NOREF#217  -  []  118.45 239.39 0 top
NOREF#218  -  []  351.34 181.37 0 top
NOREF#219  -  []  250.73 265.56 0 top
NOREF#220  -  []  167.7 138.47 90 top
NOREF#221  -  []  459.28 192.71 90 top
NOREF#222  -  []  250.18 242.88 0 top
NOREF#223  -  []  182.82 162.12 90 top
NOREF#224  -  []  332.51 265.56 0 top
NOREF#225  -  []  182.57 185.42 90 top
NOREF#226  -  []  468.85 259.9 90 top
NOREF#227  -  []  377.23 224.65 90 top
NOREF#228  -  []  388.43 180.15 0 top
NOREF#229  -  []  376.98 257.11 0 top
NOREF#230  -  []  210.86 214.75 90 top
NOREF#231  -  []  377.32 188.15 0 top
NOREF#232  -  []  201.49 146.18 90 top
NOREF#233  -  []  306.83 269.63 90 top
NOREF#234  -  []  175.7 232.37 90 top
NOREF#235  -  []  330.17 223.82 90 top
NOREF#236  -  []  320.83 254.63 0 top
NOREF#237  -  []  209.33 242.68 90 top
NOREF#238  -  []  223.56 173.86 90 top
NOREF#239  -  []  367.73 274.38 90 top
NOREF#240  -  []  413.2 164.91 90 top
NOREF#241  -  []  401.89 180.15 0 top
NOREF#242  -  []  278.6 147.38 0 top
NOREF#243  -  []  352.25 183.59 90 top
NOREF#244  -  []  386.53 148.15 90 top
NOREF#245  -  []  451.64 222.5 0 top
NOREF#246  -  []  297.71 216.09 0 top
NOREF#247  -  []  477.24 195.66 0 top
NOREF#248  -  []  352.55 183.91 0 top
NOREF#249  -  []  333.4 205.55 0 top
NOREF#250  -  []  308.36 202.16 45 top
NOREF#251  -  []  405.5 241.11 90 top
NOREF#252  -  []  309.51 186.66 0 top
NOREF#253  -  []  327.25 205.56 90 top
NOREF#254  -  []  302.92 147.32 90 top
NOREF#255  -  []  383.73 195.88 90 top
NOREF#256  -  []  473.79 234.49 90 top
NOREF#257  -  []  331.54 252.73 90 top
NOREF#258  -  []  217.41 213.24 90 top
NOREF#259  -  []  395.2 281.11 0 top
NOREF#260  -  []  285.02 288.91 90 top
NOREF#261  -  []  273.09 288.41 90 top
NOREF#262  -  []  374.08 195.9 90 top
NOREF#263  -  []  316.97 139.64 0 top
NOREF#264  -  []  93.76 287.84 90 top
NOREF#265  -  []  192.57 215.25 90 top
NOREF#266  -  []  119.7 238.84 0 top
NOREF#267  -  []  230.43 246.34 90 top
NOREF#268  -  []  263.63 225.04 90 top
NOREF#269  -  []  254.29 204.35 90 top
NOREF#270  -  []  182.57 226.57 0 top
NOREF#271  -  []  331.06 225.04 90 top
NOREF#272  -  []  252.51 265.56 90 top
NOREF#273  -  []  167.7 192.32 90 top
NOREF#274  -  []  287.91 280.1 0 top
NOREF#275  -  []  330.49 223.52 90 top
NOREF#276  -  []  282.9 147.38 0 top
NOREF#277  -  []  220.36 177.06 0 top
NOREF#278  -  []  175.8 242.68 90 top
NOREF#279  -  []  110.21 222.33 0 top
NOREF#280  -  []  302.49 296.86 0 top
NOREF#281  -  []  238.45 257.01 0 top
NOREF#282  -  []  251.38 224.74 90 top
NOREF#283  -  []  251.33 140.14 0 top
NOREF#284  -  []  391.96 131.89 0 top
NOREF#285  -  []  184.89 227.17 90 top
NOREF#286  -  []  396.03 180.15 0 top
NOREF#287  -  []  332.51 205.56 0 top
NOREF#288  -  []  230.43 193.37 90 top
NOREF#289  -  []  194.09 146.68 90 top
NOREF#290  -  []  184.47 200.54 90 top
NOREF#291  -  []  167.7 214 0 top
NOREF#292  -  []  303.15 271.32 90 top
NOREF#293  -  []  106.29 174.19 90 top
NOREF#294  -  []  167.7 173.11 0 top
NOREF#295  -  []  410.27 257.37 0 top
NOREF#296  -  []  461.86 187.32 0 top
NOREF#297  -  []  239.33 176.03 90 top
NOREF#298  -  []  383.09 257.11 0 top
NOREF#299  -  []  404.4 257.42 90 top
NOREF#300  -  []  184.47 174.46 90 top
NOREF#301  -  []  495.08 257.36 90 top
NOREF#302  -  []  115.36 235.64 0 top
NOREF#303  -  []  369.63 273.11 0 top
NOREF#304  -  []  343.98 288.86 0 top
NOREF#305  -  []  248.96 224.72 0 top
NOREF#306  -  []  483.17 130.26 90 top
NOREF#307  -  []  301.56 190.49 0 top
NOREF#308  -  []  124.35 187.53 0 top
NOREF#309  -  []  342.04 224.72 0 top
NOREF#310  -  []  108.01 195.15 0 top
NOREF#311  -  []  460.93 191.31 90 top
NOREF#312  -  []  339.65 264.65 90 top
NOREF#313  -  []  310.73 246.66 0 top
NOREF#314  -  []  238.3 163.52 90 top
NOREF#315  -  []  329.28 223.82 90 top
NOREF#316  -  []  351.04 241.69 0 top
NOREF#317  -  []  331.06 165.04 90 top
NOREF#318  -  []  201.23 186.57 0 top
NOREF#319  -  []  417.7 146.88 0 top
NOREF#320  -  []  352.55 243.91 0 top
NOREF#321  -  []  411.01 209.61 0 top
NOREF#322  -  []  272.55 185.18 0 top
NOREF#323  -  []  257.09 163.52 90 top
NOREF#324  -  []  371.73 297.12 0 top
NOREF#325  -  []  184.47 260.9 90 top
NOREF#326  -  []  184.47 159.65 0 top
NOREF#327  -  []  337.9 186.99 0 top
NOREF#328  -  []  122.19 247.3 90 top
NOREF#329  -  []  468.01 222.58 0 top
NOREF#330  -  []  35.83 132.61 0 top
NOREF#331  -  []  331.62 205.56 90 top
NOREF#332  -  []  310.43 194.01 0 top
NOREF#333  -  []  313.56 131.64 90 top
NOREF#334  -  []  199.33 199.39 0 top
NOREF#335  -  []  297.41 213.24 0 top
NOREF#336  -  []  249.85 224.74 0 top
NOREF#337  -  []  290.64 288.86 0 top
NOREF#338  -  []  396.55 289.12 0 top
NOREF#339  -  []  188.08 291.65 90 top
NOREF#340  -  []  337.9 246.99 0 top
NOREF#341  -  []  404.24 146.88 0 top
NOREF#342  -  []  209.49 162.1 90 top
NOREF#343  -  []  410.52 289.12 0 top
NOREF#344  -  []  405.93 288.57 90 top
NOREF#345  -  []  456.08 230.2 0 top
NOREF#346  -  []  414.82 281.37 0 top
NOREF#347  -  []  185.2 273.5 90 top
NOREF#348  -  []  297.83 234.63 90 top
NOREF#349  -  []  128.21 178.64 0 top
NOREF#350  -  []  310.41 243.09 90 top
NOREF#351  -  []  383.09 241.11 0 top
NOREF#352  -  []  251.38 223.52 90 top
NOREF#353  -  []  263.83 171.63 90 top
NOREF#354  -  []  272.66 288.86 90 top
NOREF#355  -  []  327.57 204.65 90 top
NOREF#356  -  []  390.69 257.11 0 top
NOREF#357  -  []  310.43 247.61 90 top
NOREF#358  -  []  381.86 129.99 0 top
NOREF#359  -  []  118.7 222.88 0 top
NOREF#360  -  []  230.83 164.63 0 top
NOREF#361  -  []  412.62 249.11 0 top
NOREF#362  -  []  495.08 277.31 90 top
NOREF#363  -  []  343.98 288.86 0 top
NOREF#364  -  []  463.11 230.2 0 top
NOREF#365  -  []  412.36 209.61 90 top
NOREF#366  -  []  209.49 150.83 90 top
NOREF#367  -  []  264.72 272.65 90 top
NOREF#368  -  []  106.36 190.55 0 top
NOREF#369  -  []  229.05 211.67 0 top
NOREF#370  -  []  407.77 255.47 0 top
NOREF#371  -  []  369.38 224.6 0 top
NOREF#372  -  []  248 286.96 0 top
NOREF#373  -  []  201.49 151.93 90 top
NOREF#374  -  []  229.21 193.37 0 top
NOREF#375  -  []  230.43 243.09 0 top
NOREF#376  -  []  396.55 241.11 0 top
NOREF#377  -  []  230.73 253.69 0 top
NOREF#378  -  []  352.25 249.82 0 top
NOREF#379  -  []  217.83 174.63 90 top
NOREF#380  -  []  411.26 209.66 90 top
NOREF#381  -  []  456.04 222.5 0 top
NOREF#382  -  []  112.05 246.78 90 top
NOREF#383  -  []  408.28 129.99 0 top
NOREF#384  -  []  272.25 244.23 0 top
NOREF#385  -  []  209.49 155.13 90 top
NOREF#386  -  []  272.8 145.48 90 top
NOREF#387  -  []  184.47 260.9 90 top
NOREF#388  -  []  381.74 265.11 0 top
NOREF#389  -  []  184.47 149.48 90 top
NOREF#390  -  []  240.83 194.63 0 top
NOREF#391  -  []  259.33 265.55 0 top
NOREF#392  -  []  252.51 264.35 90 top
NOREF#393  -  []  330.17 225.04 90 top
NOREF#394  -  []  301.56 231.46 0 top
NOREF#395  -  []  175.7 135.17 90 top
NOREF#396  -  []  327.7 131.19 90 top
NOREF#397  -  []  115.87 167.82 90 top
NOREF#398  -  []  192.57 174.36 90 top
NOREF#399  -  []  377.23 241.16 90 top
NOREF#400  -  []  168.13 172.56 90 top
NOREF#401  -  []  339.97 204.35 90 top
NOREF#402  -  []  272.25 242.32 90 top
NOREF#403  -  []  75.98 287.84 90 top
NOREF#404  -  []  378.75 224.15 90 top
NOREF#405  -  []  234.33 168.13 90 top
NOREF#406  -  []  272.55 242.64 0 top
NOREF#407  -  []  98.78 195.15 0 top
NOREF#408  -  []  390.53 171.64 0 top
NOREF#409  -  []  343.95 224.74 90 top
NOREF#410  -  []  425.7 144.98 90 top
NOREF#411  -  []  400.85 265.37 0 top
NOREF#412  -  []  231.15 159.63 90 top
NOREF#413  -  []  239.33 236.03 90 top
NOREF#414  -  []  354.37 130.67 90 top
NOREF#415  -  []  381.74 297.12 0 top
NOREF#416  -  []  405.93 288.67 90 top
NOREF#417  -  []  394.66 274.38 90 top
NOREF#418  -  []  235.85 296.61 0 top
NOREF#419  -  []  230.41 247.61 90 top
NOREF#420  -  []  418.12 241.11 0 top
NOREF#421  -  []  272.25 182.96 0 top
NOREF#422  -  []  392.24 196.98 90 top
NOREF#423  -  []  259.33 205.56 0 top
NOREF#424  -  []  369.38 241.11 0 top
NOREF#425  -  []  478.57 274.77 90 top
NOREF#426  -  []  383.83 194.68 90 top
NOREF#427  -  []  331.38 224.74 90 top
NOREF#428  -  []  290.11 280.1 0 top
NOREF#429  -  []  250.49 164.74 90 top
NOREF#430  -  []  107.76 238.84 0 top
NOREF#431  -  []  259.33 265.55 0 top
NOREF#432  -  []  118.96 174.04 90 top
NOREF#433  -  []  310.41 193.37 90 top
NOREF#434  -  []  303.56 173.86 90 top
NOREF#435  -  []  218.16 248.49 0 top
NOREF#436  -  []  165.8 240.28 90 top
NOREF#437  -  []  310.43 248.88 0 top
NOREF#438  -  []  321.82 227.13 90 top
NOREF#439  -  []  201.21 290.01 90 top
NOREF#440  -  []  528.1 273.87 90 top
NOREF#441  -  []  451.68 195.91 0 top
NOREF#442  -  []  396.55 225.11 0 top
NOREF#443  -  []  313.98 131.19 90 top
NOREF#444  -  []  352.93 288.86 90 top
NOREF#445  -  []  167.7 206.29 90 top
NOREF#446  -  []  299.59 288.86 90 top
NOREF#447  -  []  528.1 276.41 90 top
NOREF#448  -  []  383.09 224.85 0 top
NOREF#449  -  []  319.33 176.03 90 top
NOREF#450  -  []  127.99 214.79 0 top
NOREF#451  -  []  230.43 187.61 0 top
NOREF#452  -  []  168.69 290.01 90 top
NOREF#453  -  []  167.7 147.28 90 top
NOREF#454  -  []  199.33 240.28 0 top
NOREF#455  -  []  175.7 175.56 90 top
NOREF#456  -  []  352.55 181.37 0 top
NOREF#457  -  []  453.88 214.96 0 top
NOREF#458  -  []  182.57 240.28 90 top
NOREF#459  -  []  352.24 183.59 90 top
NOREF#460  -  []  184.47 247.18 90 top
NOREF#461  -  []  167.7 217.55 90 top
NOREF#462  -  []  295.19 271.65 90 top
NOREF#463  -  []  342.36 223.82 90 top
NOREF#464  -  []  412.79 209.16 90 top
NOREF#465  -  []  272.25 241.69 0 top
NOREF#466  -  []  284.77 146.93 90 top
NOREF#467  -  []  124.1 231.22 0 top
NOREF#468  -  []  263.2 172.26 90 top
NOREF#469  -  []  351.34 183.91 0 top
NOREF#470  -  []  397.8 163.19 90 top
NOREF#471  -  []  175.7 137.37 90 top
NOREF#472  -  []  253.33 181.33 90 top
NOREF#473  -  []  394.46 129.99 90 top
NOREF#474  -  []  355.89 130.17 90 top
NOREF#475  -  []  272.25 245.5 0 top
NOREF#476  -  []  230.43 254.01 0 top
NOREF#477  -  []  230.43 243.09 90 top
NOREF#478  -  []  463.61 171.53 0 top
NOREF#479  -  []  330.49 164.74 90 top
NOREF#480  -  []  310.41 253.37 90 top
NOREF#481  -  []  351.04 181.69 0 top
NOREF#482  -  []  376.23 209.11 0 top
NOREF#483  -  []  394.66 226.38 90 top
NOREF#484  -  []  237.2 296.61 0 top
NOREF#485  -  []  201.23 190.12 90 top
NOREF#486  -  []  453.84 222.5 0 top
NOREF#487  -  []  330.73 205.56 0 top
NOREF#488  -  []  192.47 257.6 90 top
NOREF#489  -  []  106.76 215.26 0 top
NOREF#490  -  []  260.29 136.46 90 top
NOREF#491  -  []  172.08 289.11 90 top
NOREF#492  -  []  221.56 182.89 0 top
NOREF#493  -  []  422.7 163.64 0 top
NOREF#494  -  []  303.47 154.05 0 top
NOREF#495  -  []  201.23 206.29 90 top
NOREF#496  -  []  105.83 190.55 90 top
NOREF#497  -  []  184.89 145.38 90 top
NOREF#498  -  []  310.73 249.2 0 top
NOREF#499  -  []  384.59 179.6 90 top
NOREF#500  -  []  209.59 160.9 90 top
NOREF#501  -  []  415.61 183.52 90 top
NOREF#502  -  []  175.8 215.25 90 top
NOREF#503  -  []  256.45 164.72 0 top
NOREF#504  -  []  471.11 186.77 0 top
NOREF#505  -  []  388.43 163.64 0 top
NOREF#506  -  []  296.96 240.71 0 top
NOREF#507  -  []  411.99 178.25 90 top
NOREF#508  -  []  192.47 162.1 90 top
NOREF#509  -  []  407.67 129.99 90 top
NOREF#510  -  []  199.59 203.01 90 top
NOREF#511  -  []  451.64 179.06 0 top
NOREF#512  -  []  528.1 259.9 90 top
NOREF#513  -  []  412.37 265.37 0 top
NOREF#514  -  []  308.14 296.86 0 top
NOREF#515  -  []  327.57 265.86 90 top
NOREF#516  -  []  247.25 265.55 0 top
NOREF#517  -  []  192.47 243.88 90 top
NOREF#518  -  []  346.27 135.17 90 top
NOREF#519  -  []  230.43 249.52 0 top
NOREF#520  -  []  83.77 247.51 90 top
NOREF#521  -  []  271.34 189.5 0 top
NOREF#522  -  []  175.7 162.1 90 top
NOREF#523  -  []  182.82 230.19 90 top
NOREF#524  -  []  471.21 211.76 0 top
NOREF#525  -  []  385.19 224.85 0 top
NOREF#526  -  []  385.61 208.56 90 top
NOREF#527  -  []  306.83 209.63 90 top
NOREF#528  -  []  210.86 242.18 90 top
NOREF#529  -  []  368.28 281.11 0 top
NOREF#530  -  []  313.22 288.41 90 top
NOREF#531  -  []  334.61 204.65 90 top
NOREF#532  -  []  394.66 242.38 90 top
NOREF#533  -  []  199.59 189.04 90 top
NOREF#534  -  []  392.47 240.56 90 top
NOREF#535  -  []  351.34 185.18 0 top
NOREF#536  -  []  271.56 134.74 90 top
NOREF#537  -  []  175.7 259.8 90 top
NOREF#538  -  []  317.66 224.74 0 top
NOREF#539  -  []  118.7 222.88 0 top
NOREF#540  -  []  392.47 256.66 90 top
NOREF#541  -  []  167.7 186.57 90 top
NOREF#542  -  []  317.05 288.86 0 top
NOREF#543  -  []  378.75 240.56 90 top
NOREF#544  -  []  182.57 144.78 0 top
NOREF#545  -  []  375.22 180.15 0 top
NOREF#546  -  []  352.55 182.64 0 top
NOREF#547  -  []  182.57 171.96 90 top
NOREF#548  -  []  379 288.57 90 top
NOREF#549  -  []  453.88 239.34 0 top
NOREF#550  -  []  410.52 241.11 0 top
NOREF#551  -  []  127.3 235.64 90 top
NOREF#552  -  []  384.59 179.7 90 top
NOREF#553  -  []  306.27 216.63 90 top
NOREF#554  -  []  324.65 288.86 0 top
NOREF#555  -  []  230.43 186.34 0 top
NOREF#556  -  []  311.69 288.91 90 top
NOREF#557  -  []  460.89 174.46 90 top
NOREF#558  -  []  354.27 131.87 90 top
NOREF#559  -  []  230.43 193.37 0 top
NOREF#560  -  []  451.68 171.53 0 top
NOREF#561  -  []  247.57 205.86 90 top
NOREF#562  -  []  351.34 249.5 0 top
NOREF#563  -  []  209.23 216.45 90 top
NOREF#564  -  []  327.57 205.86 90 top
NOREF#565  -  []  310.73 193.69 0 top
NOREF#566  -  []  406.19 188.15 0 top
NOREF#567  -  []  301.56 250.49 0 top
NOREF#568  -  []  238.3 288.61 0 top
NOREF#569  -  []  261.63 233.83 90 top
NOREF#570  -  []  327.89 264.35 90 top
NOREF#571  -  []  336.77 163.82 90 top
NOREF#572  -  []  106.76 217.73 90 top
NOREF#573  -  []  346.08 296.86 0 top
NOREF#574  -  []  417.2 163.64 0 top
NOREF#575  -  []  229.21 183.09 0 top
NOREF#576  -  []  310.73 187.93 0 top
NOREF#577  -  []  392.24 194.78 90 top
NOREF#578  -  []  379.52 188.15 0 top
NOREF#579  -  []  168.69 276.04 90 top
NOREF#580  -  []  412.88 131.89 0 top
NOREF#581  -  []  192.47 150.58 90 top
NOREF#582  -  []  399.64 144.98 0 top
NOREF#583  -  []  390.69 289.12 0 top
NOREF#584  -  []  237.57 269.63 90 top
NOREF#585  -  []  419.73 131.89 90 top
NOREF#586  -  []  383.09 289.12 0 top
NOREF#587  -  []  94.68 234.24 0 top
NOREF#588  -  []  119.95 187.53 0 top
NOREF#589  -  []  351.34 243.91 0 top
NOREF#590  -  []  234.7 286.71 90 top
NOREF#591  -  []  248.96 164.74 0 top
NOREF#592  -  []  302.11 180.71 0 top
NOREF#593  -  []  463.61 222.58 0 top
NOREF#594  -  []  232.25 271.67 90 top
NOREF#595  -  []  450.03 191.31 0 top
NOREF#596  -  []  303.84 288.86 0 top
NOREF#597  -  []  167.7 242.78 90 top
NOREF#598  -  []  351.34 242.64 0 top
NOREF#599  -  []  387.08 171.64 0 top
NOREF#600  -  []  546.67 300.44 90 top
NOREF#601  -  []  304.82 146.05 0 top
NOREF#602  -  []  369.38 224.6 0 top
NOREF#603  -  []  250.73 204.35 90 top
NOREF#604  -  []  328.96 224.74 0 top
NOREF#605  -  []  257.9 246.35 90 top
NOREF#606  -  []  216.96 192.14 0 top
NOREF#607  -  []  253.72 265.86 90 top
NOREF#608  -  []  391.8 209.36 0 top
NOREF#609  -  []  155.57 272.6 90 top
NOREF#610  -  []  192.57 187.82 90 top
NOREF#611  -  []  399.8 207.46 90 top
NOREF#612  -  []  230.73 249.2 0 top
NOREF#613  -  []  352.25 181.69 0 top
NOREF#614  -  []  118.33 286.94 90 top
NOREF#615  -  []  184.47 244.98 90 top
NOREF#616  -  []  411.99 161.74 90 top
NOREF#617  -  []  120.24 171.1 0 top
NOREF#618  -  []  209.23 243.88 90 top
NOREF#619  -  []  351.34 182.64 0 top
NOREF#620  -  []  229.51 253.69 0 top
NOREF#621  -  []  229.21 247.61 0 top
NOREF#622  -  []  201.66 240.88 90 top
NOREF#623  -  []  88.64 247.45 90 top
NOREF#624  -  []  321.35 296.86 0 top
NOREF#625  -  []  167.7 247.18 90 top
NOREF#626  -  []  467.51 230.2 0 top
NOREF#627  -  []  385.18 209.11 90 top
NOREF#628  -  []  322.23 173.13 90 top
NOREF#629  -  []  351.04 182.96 0 top
NOREF#630  -  []  274.67 286.96 0 top
NOREF#631  -  []  272.24 182.32 90 top
NOREF#632  -  []  410.52 273.37 0 top
NOREF#633  -  []  310.43 193.37 0 top
NOREF#634  -  []  175.7 243.88 90 top
NOREF#635  -  []  118.7 195.7 0 top
NOREF#636  -  []  405.5 273.11 90 top
NOREF#637  -  []  342.08 290.13 90 top
NOREF#638  -  []  256.45 224.72 0 top
NOREF#639  -  []  354.08 286.96 90 top
NOREF#640  -  []  112.41 222.33 0 top
NOREF#641  -  []  182.82 216.47 90 top
NOREF#642  -  []  337.09 164.74 90 top
NOREF#643  -  []  115.87 175.44 90 top
NOREF#644  -  []  317.66 164.72 0 top
NOREF#645  -  []  210.86 228.47 90 top
NOREF#646  -  []  339.65 205.86 90 top
NOREF#647  -  []  250.49 223.52 90 top
NOREF#648  -  []  246.63 130.24 90 top
NOREF#649  -  []  390.53 163.64 0 top
NOREF#650  -  []  383.09 289.12 0 top
NOREF#651  -  []  400.91 207.71 0 top
NOREF#652  -  []  373.93 281.11 0 top
NOREF#653  -  []  495.08 274.77 90 top
NOREF#654  -  []  330.73 205.55 0 top
NOREF#655  -  []  241.82 167.13 90 top
NOREF#656  -  []  371.48 224.6 0 top
NOREF#657  -  []  415.08 139.89 0 top
NOREF#658  -  []  230.41 186.34 90 top
NOREF#659  -  []  367.13 271.21 0 top
NOREF#660  -  []  343.95 223.52 90 top
NOREF#661  -  []  201.49 149.73 90 top
NOREF#662  -  []  127.84 167.9 90 top
NOREF#663  -  []  165.8 212.85 90 top
NOREF#664  -  []  230.41 253.37 90 top
NOREF#665  -  []  122.15 195.15 0 top
NOREF#666  -  []  313.22 288.31 90 top
NOREF#667  -  []  373.83 192.28 90 top
NOREF#668  -  []  272.25 249.82 0 top
NOREF#669  -  []  461.86 230.75 0 top
NOREF#670  -  []  226.85 211.67 0 top
NOREF#671  -  []  334.29 265.56 90 top
NOREF#672  -  []  96.33 238.84 0 top
NOREF#673  -  []  406.65 287.22 90 top
NOREF#674  -  []  271.04 249.18 0 top
NOREF#675  -  []  394.05 239.21 0 top
NOREF#676  -  []  184.89 199.99 90 top
NOREF#677  -  []  414.82 297.12 0 top
NOREF#678  -  []  247.25 265.55 0 top
NOREF#679  -  []  309.21 183.09 0 top
NOREF#680  -  []  375.22 180.15 0 top
NOREF#681  -  []  210.86 187.32 90 top
NOREF#682  -  []  397.57 131.89 0 top
NOREF#683  -  []  251.38 164.74 90 top
NOREF#684  -  []  339.33 264.35 90 top
NOREF#685  -  []  327.25 205.55 0 top
NOREF#686  -  []  93.76 290.38 90 top
NOREF#687  -  []  248.96 164.72 0 top
NOREF#688  -  []  511.59 259.9 90 top
NOREF#689  -  []  230.43 247.61 90 top
NOREF#690  -  []  199.33 185.42 90 top
NOREF#691  -  []  408.63 242.38 90 top
